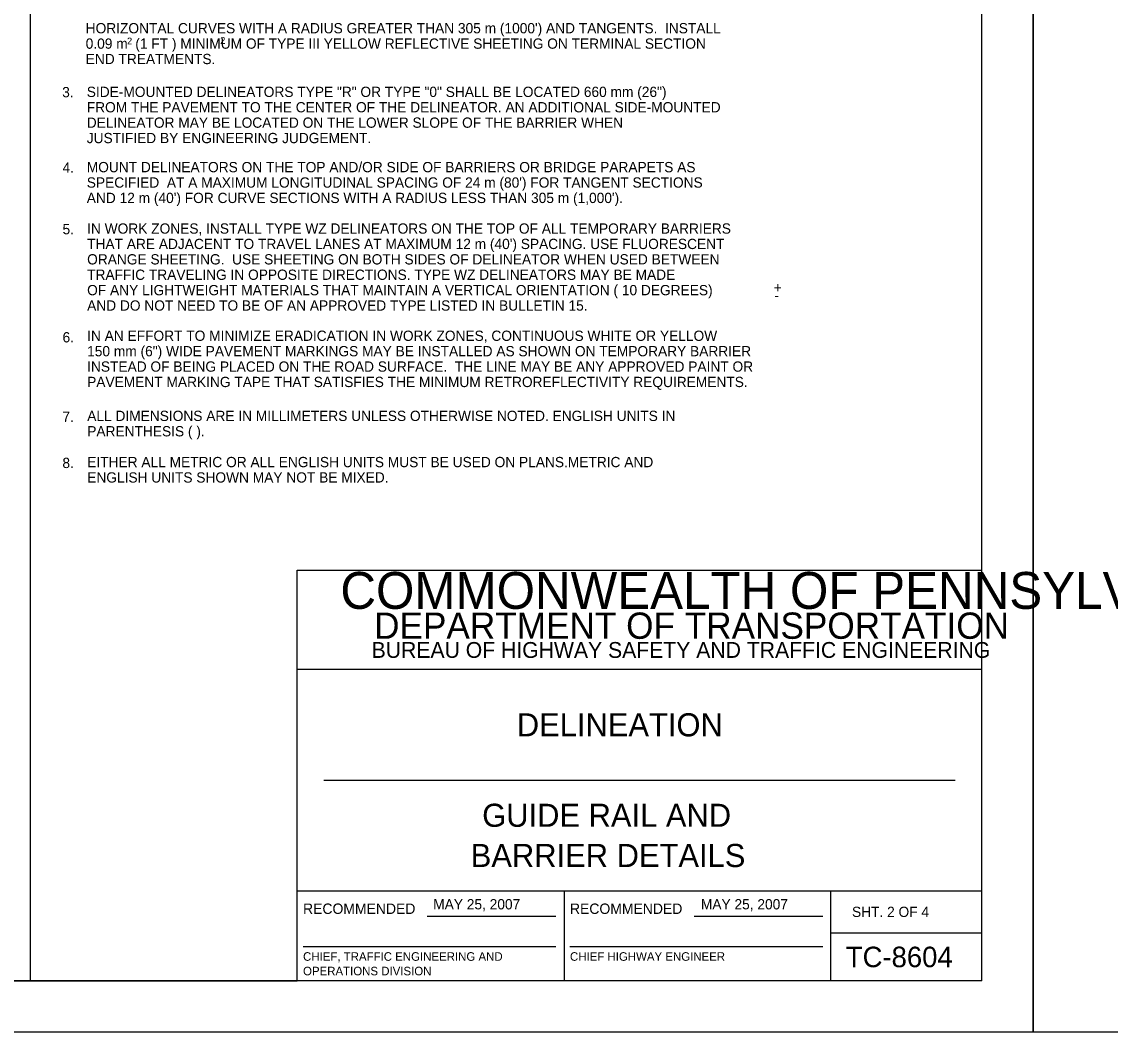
# Model space of a CAD drawing. Extents: x 640253 to 641999, y 298458 to 299646.
# Drawn here: x 640798.8 to 641116.9, y 298457.6 to 298753 of the extents above; entities that cross this region are included whole.
import ezdxf

# ---------------------------------------------------------------- set-up
doc = ezdxf.new("R2010")
doc.units = 0
for name, color, linetype in [('1', 7, 'Continuous'), ('2', 7, 'Continuous'), ('PLT-BNDY', 7, 'Continuous')]:
    doc.layers.add(name, color=color, linetype=linetype)

msp = doc.modelspace()

# ---------------------------------------------------------------- linework, layer by layer
at = {"layer": '1'}
for p, q in [((640801.38, 298472.63), (640801.38, 299036.63)), ((641079.31, 298472.63), (641079.31, 299036.63)), ((640879.31, 298472.63), (640879.31, 298592.63)), ((640879.31, 298592.63), (641079.31, 298592.63)), ((641079.31, 298563.63), (640879.31, 298563.63)), ((640887.06, 298531.31), (641071.56, 298531.31)), ((640879.31, 298499), (641079.31, 298499)), ((640957.31, 298499), (640957.31, 298472.63)), ((641035.19, 298472.63), (641035.19, 298499)), ((640917.24, 298491.57), (640954.87, 298491.57)), ((640995.24, 298491.57), (641032.87, 298491.57)), ((641035.19, 298486.63), (641079.31, 298486.63)), ((640880.99, 298482.68), (640954.87, 298482.68)), ((640958.99, 298482.68), (641032.87, 298482.68)), ((641079.31, 298472.63), (640293.31, 298472.63)), ((640293.31, 298472.63), (640879.31, 298472.63))]:
    msp.add_line(p, q, dxfattribs=at)
at = {"layer": 'PLT-BNDY'}
for points in [[(640253.31, 299051.63), (641094.31, 299051.63), (641094.31, 298457.63), (640253.31, 298457.63)], [(641094.31, 299051.63), (641935.31, 299051.63), (641935.31, 298457.63), (641094.31, 298457.63)]]:
    msp.add_lwpolyline(points, close=True, dxfattribs=at)

# ---------------------------------------------------------------- texts
at = {"layer": '1'}
for s, height, p in [('COMMONWEALTH OF PENNSYLVANIA', 10.7828, (640891.9, 298581.36)), ('DEPARTMENT OF TRANSPORTATION', 7.6837, (640901.76, 298572.61)), ('BUREAU OF HIGHWAY SAFETY AND TRAFFIC ENGINEERING', 4.6253, (640901.04, 298567.04)), ('DELINEATION', 6.75, (640943.46, 298544.1)), ('GUIDE RAIL AND', 6.75, (640933.34, 298517.66)), ('BARRIER DETAILS', 6.75, (640929.99, 298505.91)), ('RECOMMENDED', 3.048, (640880.99, 298492.2)), ('RECOMMENDED', 3.048, (640958.99, 298492.2)), ('SHT. 2 OF 4', 3, (641041.4, 298491.31)), ('TC-8604', 6, (641039.6, 298476.63)), ('CHIEF, TRAFFIC ENGINEERING AND', 2.5, (640880.99, 298478.51)), ('CHIEF HIGHWAY ENGINEER', 2.5, (640958.99, 298478.51)), ('OPERATIONS DIVISION', 2.5, (640880.99, 298474.26))]:
    msp.add_text(s, height=height, dxfattribs=at).set_placement(p)
at = {"layer": '2'}
for s, height, p in [("HORIZONTAL CURVES WITH A RADIUS GREATER THAN 305 m (1000') AND TANGENTS.  INSTALL", 3, (640817.48, 298749.57)), ('0.09 m  (1 FT ) MINIMUM OF TYPE III YELLOW REFLECTIVE SHEETING ON TERMINAL SECTION', 3, (640817.48, 298745.07)), ('2', 2, (640829.57, 298746.32)), ('2', 2, (640856.8, 298746.5)), ('END TREATMENTS.', 3, (640817.48, 298740.57)), ('3.', 3, (640810.61, 298730.89)), ('SIDE-MOUNTED DELINEATORS TYPE "R" OR TYPE "0" SHALL BE LOCATED 660 mm (26") ', 3, (640817.79, 298730.97)), ('FROM THE PAVEMENT TO THE CENTER OF THE DELINEATOR. AN ADDITIONAL SIDE-MOUNTED ', 3, (640817.79, 298726.47)), ('DELINEATOR MAY BE LOCATED ON THE LOWER SLOPE OF THE BARRIER WHEN ', 3, (640817.79, 298721.97)), ('JUSTIFIED BY ENGINEERING JUDGEMENT.', 3, (640817.79, 298717.47)), ('4.', 3, (640810.71, 298708.82)), ('MOUNT DELINEATORS ON THE TOP AND/OR SIDE OF BARRIERS OR BRIDGE PARAPETS AS ', 3, (640817.79, 298708.97)), ("SPECIFIED  AT A MAXIMUM LONGITUDINAL SPACING OF 24 m (80') FOR TANGENT SECTIONS ", 3, (640817.79, 298704.47)), ("AND 12 m (40') FOR CURVE SECTIONS WITH A RADIUS LESS THAN 305 m (1,000').", 3, (640817.79, 298699.97)), ('5.', 3, (640810.71, 298690.84)), ('IN WORK ZONES, INSTALL TYPE WZ DELINEATORS ON THE TOP OF ALL TEMPORARY BARRIERS', 3, (640817.9, 298691.02)), ("THAT ARE ADJACENT TO TRAVEL LANES AT MAXIMUM 12 m (40') SPACING. USE FLUORESCENT ", 3, (640817.9, 298686.52)), ('ORANGE SHEETING.  USE SHEETING ON BOTH SIDES OF DELINEATOR WHEN USED BETWEEN', 3, (640817.9, 298682.02)), ('TRAFFIC TRAVELING IN OPPOSITE DIRECTIONS. TYPE WZ DELINEATORS MAY BE MADE', 3, (640817.9, 298677.52)), ('+', 3, (641018.54, 298673.75)), ('OF ANY LIGHTWEIGHT MATERIALS THAT MAINTAIN A VERTICAL ORIENTATION ( 10 DEGREES) ', 3, (640817.9, 298673.02)), ('AND DO NOT NEED TO BE OF AN APPROVED TYPE LISTED IN BULLETIN 15.', 3, (640817.9, 298668.52)), ('-', 3, (641018.75, 298671.51)), ('6.', 3, (640810.71, 298659.24)), ('IN AN EFFORT TO MINIMIZE ERADICATION IN WORK ZONES, CONTINUOUS WHITE OR YELLOW ', 3, (640817.9, 298659.68)), ('150 mm (6") WIDE PAVEMENT MARKINGS MAY BE INSTALLED AS SHOWN ON TEMPORARY BARRIER ', 3, (640817.9, 298655.18)), ('INSTEAD OF BEING PLACED ON THE ROAD SURFACE.  THE LINE MAY BE ANY APPROVED PAINT OR ', 3, (640817.9, 298650.68)), ('PAVEMENT MARKING TAPE THAT SATISFIES THE MINIMUM RETROREFLECTIVITY REQUIREMENTS.', 3, (640817.9, 298646.18)), ('7.', 3, (640810.68, 298636.02)), ('ALL DIMENSIONS ARE IN MILLIMETERS UNLESS OTHERWISE NOTED. ENGLISH UNITS IN ', 3, (640817.93, 298636.27)), ('PARENTHESIS ( ).', 3, (640817.93, 298631.77)), ('8.', 3, (640810.68, 298622.52)), ('EITHER ALL METRIC OR ALL ENGLISH UNITS MUST BE USED ON PLANS.METRIC AND ', 3, (640817.93, 298622.77)), ('ENGLISH UNITS SHOWN MAY NOT BE MIXED.', 3, (640817.93, 298618.27)), ('MAY 25, 2007', 3, (640919.03, 298493.53)), ('MAY 25, 2007', 3, (640997.25, 298493.53))]:
    msp.add_text(s, height=height, dxfattribs=at).set_placement(p)

doc.saveas('drawing.dxf')
